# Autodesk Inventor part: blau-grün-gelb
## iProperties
Created: 2004-10
Part Number: blau-grün-gelb
Document SubType Name: Modeling
Designer: sahrens
Manufacturer: Standard
Standards Organization: Custom
Author: sahrens
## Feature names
1. Extrusion1
2. Rundung2 [Fillet]
